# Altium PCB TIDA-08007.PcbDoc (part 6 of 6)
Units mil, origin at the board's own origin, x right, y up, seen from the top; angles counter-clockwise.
Board outline 4212.6 x 2047.24 mil, 10 copper layers (Top Layer, GND 1, Signal Layer 1, GND 2, Split PWR 1, Split PWR 2, GND 3, Signal Layer 2, GND 4, Bottom Layer), stack 66.4 mil thick; 291 components, 178 nets, 1281 pads, 873 vias.
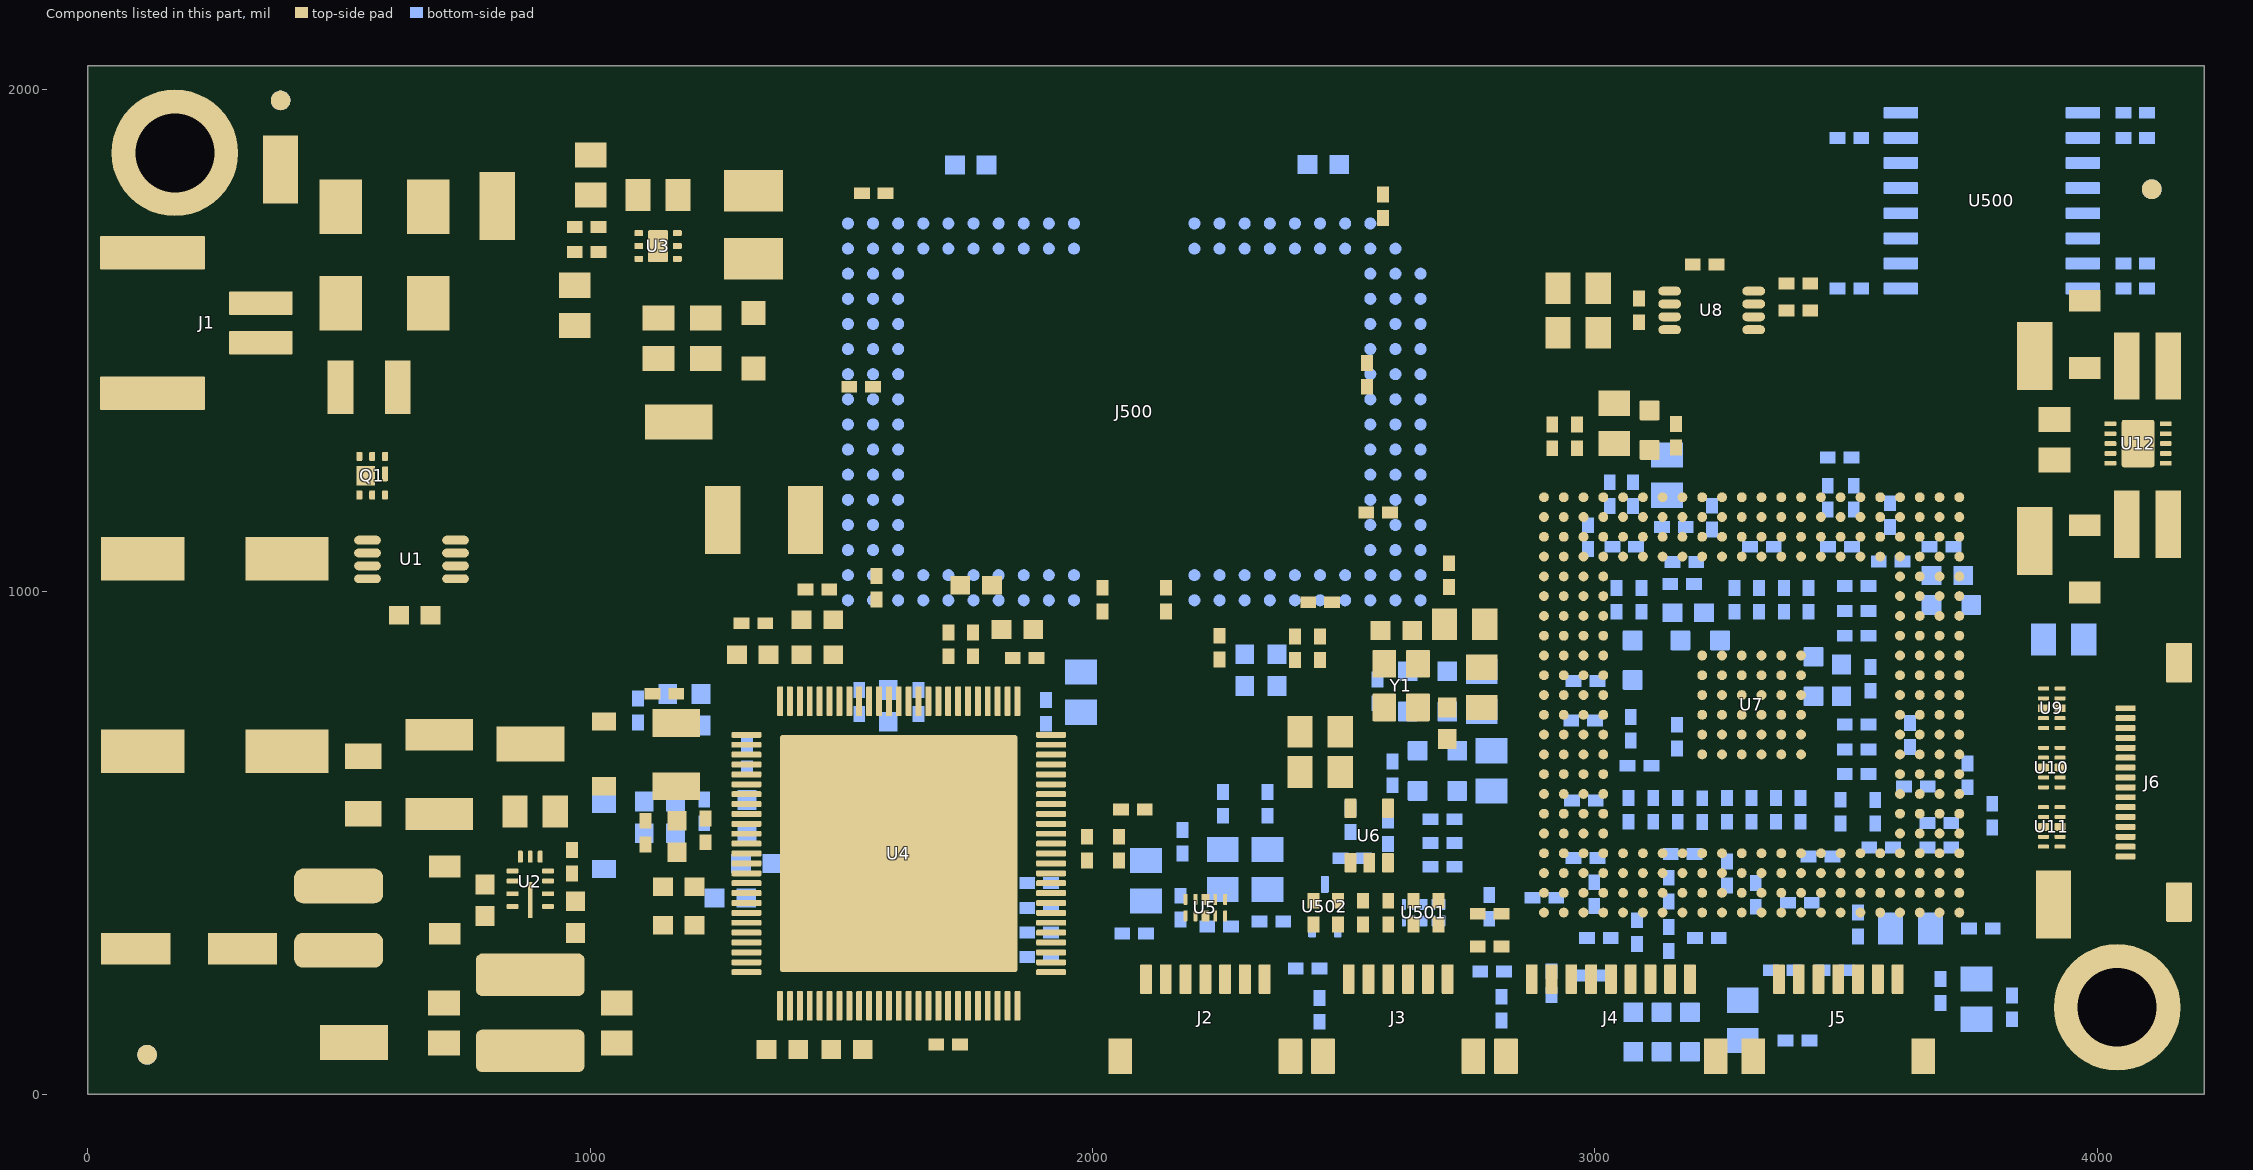
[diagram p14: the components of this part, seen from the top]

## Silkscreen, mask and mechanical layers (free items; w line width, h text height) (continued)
M12 Stackup:
  drawing of 635 lines, arcs and shapes, not listed
  text "LAYER STACKUP" at 6174.36,7399.92 h80
  text "Layer" at 6236.3,7217.54 h60
  text "Name" at 6646.22,7217.54 h60
  text "Material" at 7585.96,7217.54 h60
  text "Thickness" at 8445.72,7217.54 h60
  text "Constant" at 9095.56,7217.54 h60
  text "Board Layer Stack" at 9665.42,7217.54 h60
  text "1" at 6236.3,7097.54 h60
  text "Top Overlay" at 6646.22,7097.54 h60
  text "2" at 6236.3,6977.54 h60
  text "Top Solder" at 6646.22,6977.54 h60
  text "Solder Resist" at 7585.96,6977.54 h60
  text "0.80mil" at 8445.72,6977.54 h60
  text "3.3" at 9095.56,6977.54 h60
  text "3" at 5944.54,6876 h60
  text "5" at 6062.59,6875.94 h60
  text "3" at 6236.3,6857.54 h60
  text "Top Layer" at 6646.22,6857.54 h60
  text "Copper" at 7585.96,6857.54 h60
  text "1.60mil" at 8445.72,6857.54 h60
  text "4" at 6236.3,6737.54 h60
  text "Dielectric 1" at 6646.22,6737.54 h60
  text "FR-4" at 7585.96,6737.54 h60
  text "4.00mil" at 8445.72,6737.54 h60
  text "4.2" at 9095.56,6737.54 h60
  text "5" at 6236.3,6617.54 h60
  text "GND 1" at 6646.22,6617.54 h60
  text "Copper" at 7585.96,6617.54 h60
  text "1.40mil" at 8445.72,6617.54 h60
  text "6" at 6236.3,6497.54 h60
  text "Dielectric 2" at 6646.22,6497.54 h60
  text "FR-4" at 7585.96,6497.54 h60
  text "8.00mil" at 8445.72,6497.54 h60
  text "4.2" at 9095.56,6497.54 h60
  text "4" at 5944.54,6396 h60
  text "6" at 6062.59,6395.94 h60
  text "7" at 6236.3,6377.54 h60
  text "Signal Layer 1" at 6646.22,6377.54 h60
  text "Copper" at 7585.96,6377.54 h60
  text "1.40mil" at 8445.72,6377.54 h60
  text "8" at 6236.3,6257.54 h60
  text "Dielectric 3" at 6646.22,6257.54 h60
  text "FR-4" at 7585.96,6257.54 h60
  text "8.00mil" at 8445.72,6257.54 h60
  text "4.2" at 9095.56,6257.54 h60
  text "9" at 6236.3,6137.54 h60
  text "GND 2" at 6646.22,6137.54 h60
  text "Copper" at 7585.96,6137.54 h60
  text "1.40mil" at 8445.72,6137.54 h60
  text "10" at 6236.3,6017.54 h60
  text "Dielectric 4" at 6646.22,6017.54 h60
  text "FR-4" at 7585.96,6017.54 h60
  text "4.00mil" at 8445.72,6017.54 h60
  text "4.2" at 9095.56,6017.54 h60
  text "11" at 6236.3,5897.54 h60
  text "Split PWR 1" at 6646.22,5897.54 h60
  text "Copper" at 7585.96,5897.54 h60
  text "1.40mil" at 8445.72,5897.54 h60
  text "12" at 6236.3,5777.54 h60
  text "Dielectric 5" at 6646.22,5777.54 h60
  text "FR-4" at 7585.96,5777.54 h60
  text "4.00mil" at 8445.72,5777.54 h60
  text "4.2" at 9095.56,5777.54 h60
  text "13" at 6236.3,5657.54 h60
  text "Split PWR 2" at 6646.22,5657.54 h60
  text "Copper" at 7585.96,5657.54 h60
  text "1.40mil" at 8445.72,5657.54 h60
  text "14" at 6236.3,5537.54 h60
  text "Dielectric 6" at 6646.22,5537.54 h60
  text "FR-4" at 7585.96,5537.54 h60
  text "4.00mil" at 8445.72,5537.54 h60
  text "4.2" at 9095.56,5537.54 h60
  text "15" at 6236.3,5417.54 h60
  text "GND 3" at 6646.22,5417.54 h60
  text "Copper" at 7585.96,5417.54 h60
  text "1.40mil" at 8445.72,5417.54 h60
  text "16" at 6236.3,5297.54 h60
  text "Dielectric 7" at 6646.22,5297.54 h60
  text "FR-4" at 7585.96,5297.54 h60
  text "8.00mil" at 8445.72,5297.54 h60
  text "4.2" at 9095.56,5297.54 h60
  text "4" at 5944.54,5196 h60
  text "6" at 6062.59,5195.94 h60
  text "17" at 6236.3,5177.54 h60
  text "Signal Layer 2" at 6646.22,5177.54 h60
  text "Copper" at 7585.96,5177.54 h60
  text "1.40mil" at 8445.72,5177.54 h60
  text "18" at 6236.3,5057.54 h60
  text "Dielectric 8" at 6646.22,5057.54 h60
  text "FR-4" at 7585.96,5057.54 h60
  text "8.00mil" at 8445.72,5057.54 h60
  text "4.2" at 9095.56,5057.54 h60
  text "19" at 6236.3,4937.54 h60
  text "GND 4" at 6646.22,4937.54 h60
  text "Copper" at 7585.96,4937.54 h60
  text "1.40mil" at 8445.72,4937.54 h60
  text "20" at 6236.3,4817.54 h60
  text "Dielectric 9" at 6646.22,4817.54 h60
  text "FR-4" at 7585.96,4817.54 h60
  text "4.00mil" at 8445.72,4817.54 h60
  text "4.2" at 9095.56,4817.54 h60
  text "3" at 6062.59,4715.94 h60
  text "21" at 6236.3,4697.54 h60
  text "Bottom Layer" at 6646.22,4697.54 h60
  text "Copper" at 7585.96,4697.54 h60
  text "1.60mil" at 8445.72,4697.54 h60
  text "22" at 6236.3,4577.54 h60
  text "Bottom Solder" at 6646.22,4577.54 h60
  text "Solder Resist" at 7585.96,4577.54 h60
  text "0.80mil" at 8445.72,4577.54 h60
  text "3.3" at 9095.56,4577.54 h60
  text "23" at 6236.3,4457.54 h60
  text "Bottom Overlay" at 6646.22,4457.54 h60
  text "THIS IS AN IMPEDANCE CONTROLLED BOARD" at 7029.46,4303.75 h80
  text "NOTE:" at 5729.52,4072.35 h80
  text "1. ALL CORE AND PREPREG THICKNESSES ARE UP TO FAB SHOP TO SELECT." at 5729.52,3902.42 h80
  text "2. EXTERNAL LAYER CU THICKNESSES ARE FINISHED THICKNESS AFTER PLATING." at 5729.52,3716.04 h80
M13 Component Bodies Top:
  text ".Layer_Name" at 577,-858.49 h60
M14 Component Bodies Bottom:
  text ".Layer_Name" at 577,-858.49 h60
M15 Courtyards Top:
  lines w10: 610.24,374.02 3562.99,374.02 3562.99,2047.24 610.24,2047.24 610.24,374.02
  text "Heatsink area. No components taller than 3mm allowed within this area" at 1496.06,403.54 h72.83
  text ".Layer_Name" at 577,-858.49 h60
M16 Courtyards Bottom:
  text ".Layer_Name" at 577,-858.49 h60
Drill Drawing:
  lines w12: 6107.35,2087.43 11008.02,2087.43 ; 6107.35,2837.43 11008.02,2837.43 ; 6658.22,1937.43 6658.22,2987.43 ; 7296.05,1937.43 7296.05,2987.43 ; 8641.66,1937.43 8641.66,2987.43 ; 9147.53,1937.43 9147.53,2987.43 ; 9881.34,1937.43 9881.34,2987.43 ; 6107.35,1937.43 11008.02,1937.43 11008.02,2987.43 6107.35,2987.43 6107.35,1937.43
  text "DRILL TABLE" at 6109.19,3036.15 h80
  text "Symbol" at 6197.35,2882.43 h72
  text "Quantity" at 6703.22,2882.43 h72
  text "Finished Hole Size" at 7341.05,2882.43 h72
  text "Plated" at 8686.66,2882.43 h72
  text "Hole Type" at 9192.53,2882.43 h72
  text "Hole Tolerance" at 9926.34,2882.43 h72
  text "87" at 6703.22,2732.43 h60
  text "7.87mil (0.200mm)" at 7341.05,2732.43 h60
  text "PTH" at 8686.66,2732.43 h60
  text "Round" at 9192.53,2732.43 h60
  text "+0/-7.87mil" at 9926.34,2732.43 h60
  text "A" at 6168.26,2722.44 h66.67
  text "335" at 6703.22,2582.43 h60
  text "8.00mil (0.203mm)" at 7341.05,2582.43 h60
  text "PTH" at 8686.66,2582.43 h60
  text "Round" at 9192.53,2582.43 h60
  text "+0/-8mil" at 9926.34,2582.43 h60
  text "B" at 6168.26,2572.44 h66.67
  text "439" at 6703.22,2432.43 h60
  text "10.00mil (0.254mm)" at 7341.05,2432.43 h60
  text "PTH" at 8686.66,2432.43 h60
  text "Round" at 9192.53,2432.43 h60
  text "+0/-10mil" at 9926.34,2432.43 h60
  text "C" at 6168.26,2422.44 h66.67
  text "12" at 6703.22,2282.43 h60
  text "19.69mil (0.500mm)" at 7341.05,2282.43 h60
  text "PTH" at 8686.66,2282.43 h60
  text "Round" at 9192.53,2282.43 h60
  text "+/-3mil" at 9926.34,2282.43 h60
  text "D" at 6168.26,2272.44 h66.67
  text "2" at 6703.22,2132.43 h60
  text "157.00mil (3.988mm)" at 7341.05,2132.43 h60
  text "PTH" at 8686.66,2132.43 h60
  text "Round" at 9192.53,2132.43 h60
  text "+/-3mil" at 9926.34,2132.43 h60
  text "E" at 6168.26,2122.44 h66.67
  text "875 Total" at 6703.22,1982.43 h60
  text "FAB" at 577,-858.49 h60
Mechanical 17:
  text ".Layer_Name" at 577,-858.49 h60
Mechanical 18:
  text ".Layer_Name" at 577,-858.49 h60
Mechanical 19:
  text ".Layer_Name" at 577,-858.49 h60

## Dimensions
-10.24,-11.75 to -117.82,-97.53 on M2 Board Dimensions
4039.37,173.23 to 4212.6,0 on M2 Board Dimensions
0,0 to 4039.37,173.23 on M2 Board Dimensions
173.23,1874.02 to 0,0 on M2 Board Dimensions
0,2047.24 to 173.23,1874.02 on M2 Board Dimensions
0,-400 to 1000,-400 on M2 Board Dimensions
